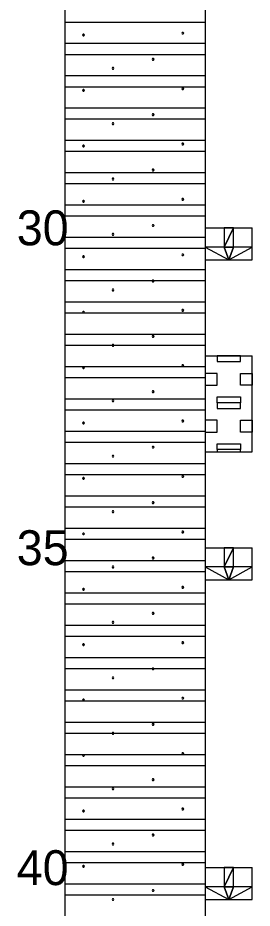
# Model space of a CAD drawing. Extents: x 2150161.5 to 2150203.1, y 143779.5 to 143868.5.
# Drawn here: x 2150192.011 to 2150192.844, y 143846.209 to 143849.371 of the extents above; entities that cross this region are included whole.
import ezdxf

# ---------------------------------------------------------------- set-up
doc = ezdxf.new("R2010")
doc.units = 0
doc.layers.add('Default', color=7, linetype='Continuous')

msp = doc.modelspace()

# ---------------------------------------------------------------- linework, layer by layer
at = {"layer": 'Default'}
for points in [[(2150192.1772, 143855.4435), (2150192.1772, 143843.2844)], [(2150192.6772, 143855.4435), (2150192.6772, 143843.2844)], [(2150192.1772, 143849.3564), (2150192.6772, 143849.3564)], [(2150192.2476, 143849.3102), (2150192.2459, 143849.313), (2150192.2427, 143849.313), (2150192.241, 143849.3102), (2150192.2427, 143849.3073), (2150192.2459, 143849.3073), (2150192.2476, 143849.3102)], [(2150192.6003, 143849.3167), (2150192.5987, 143849.3196), (2150192.5954, 143849.3196), (2150192.5938, 143849.3167), (2150192.5954, 143849.3139), (2150192.5987, 143849.3139), (2150192.6003, 143849.3167)], [(2150192.1772, 143849.2809), (2150192.6772, 143849.2809)], [(2150192.1772, 143849.2415), (2150192.6772, 143849.2415)], [(2150192.4948, 143849.2242), (2150192.4932, 143849.227), (2150192.4899, 143849.227), (2150192.4883, 143849.2242), (2150192.4899, 143849.2213), (2150192.4932, 143849.2213), (2150192.4948, 143849.2242)], [(2150192.1772, 143849.1661), (2150192.6772, 143849.1661)], [(2150192.3522, 143849.1923), (2150192.3506, 143849.1952), (2150192.3473, 143849.1952), (2150192.3457, 143849.1923), (2150192.3473, 143849.1894), (2150192.3506, 143849.1894), (2150192.3522, 143849.1923)], [(2150192.1772, 143849.1267), (2150192.6772, 143849.1267)], [(2150192.2476, 143849.1133), (2150192.2459, 143849.1161), (2150192.2427, 143849.1161), (2150192.241, 143849.1133), (2150192.2427, 143849.1104), (2150192.2459, 143849.1104), (2150192.2476, 143849.1133)], [(2150192.6003, 143849.1198), (2150192.5987, 143849.1227), (2150192.5954, 143849.1227), (2150192.5938, 143849.1198), (2150192.5954, 143849.117), (2150192.5987, 143849.117), (2150192.6003, 143849.1198)], [(2150192.1772, 143849.0513), (2150192.6772, 143849.0513)], [(2150192.1772, 143849.0119), (2150192.6772, 143849.0119)], [(2150192.4948, 143849.0273), (2150192.4932, 143849.0301), (2150192.4899, 143849.0301), (2150192.4883, 143849.0273), (2150192.4899, 143849.0245), (2150192.4932, 143849.0245), (2150192.4948, 143849.0273)], [(2150192.3522, 143848.9954), (2150192.3506, 143848.9983), (2150192.3473, 143848.9983), (2150192.3457, 143848.9955), (2150192.3473, 143848.9926), (2150192.3506, 143848.9926), (2150192.3522, 143848.9954)], [(2150192.1772, 143848.9364), (2150192.6772, 143848.9364)], [(2150192.2476, 143848.9165), (2150192.2459, 143848.9193), (2150192.2427, 143848.9193), (2150192.241, 143848.9165), (2150192.2427, 143848.9136), (2150192.2459, 143848.9136), (2150192.2476, 143848.9165)], [(2150192.6003, 143848.923), (2150192.5987, 143848.9259), (2150192.5954, 143848.9259), (2150192.5938, 143848.923), (2150192.5954, 143848.9202), (2150192.5987, 143848.9202), (2150192.6003, 143848.923)], [(2150192.1772, 143848.8971), (2150192.6772, 143848.8971)], [(2150192.1772, 143848.8216), (2150192.6772, 143848.8216)], [(2150192.4948, 143848.8305), (2150192.4932, 143848.8333), (2150192.4899, 143848.8333), (2150192.4883, 143848.8305), (2150192.4899, 143848.8276), (2150192.4932, 143848.8276), (2150192.4948, 143848.8305)], [(2150192.3522, 143848.7986), (2150192.3506, 143848.8015), (2150192.3473, 143848.8015), (2150192.3457, 143848.7986), (2150192.3473, 143848.7957), (2150192.3506, 143848.7957), (2150192.3522, 143848.7986)], [(2150192.1772, 143848.7822), (2150192.6772, 143848.7822)], [(2150192.2476, 143848.7196), (2150192.2459, 143848.7224), (2150192.2427, 143848.7224), (2150192.241, 143848.7196), (2150192.2427, 143848.7167), (2150192.2459, 143848.7167), (2150192.2476, 143848.7196)], [(2150192.6003, 143848.7261), (2150192.5987, 143848.729), (2150192.5954, 143848.729), (2150192.5938, 143848.7261), (2150192.5954, 143848.7233), (2150192.5987, 143848.7233), (2150192.6003, 143848.7261)], [(2150192.1772, 143848.7068), (2150192.6772, 143848.7068)], [(2150192.1772, 143848.6674), (2150192.6772, 143848.6674)], [(2150192.4948, 143848.6336), (2150192.4932, 143848.6364), (2150192.4899, 143848.6364), (2150192.4883, 143848.6336), (2150192.4899, 143848.6308), (2150192.4932, 143848.6308), (2150192.4948, 143848.6336)], [(2150192.3522, 143848.6017), (2150192.3506, 143848.6046), (2150192.3473, 143848.6046), (2150192.3457, 143848.6018), (2150192.3473, 143848.5989), (2150192.3506, 143848.5989), (2150192.3522, 143848.6017)], [(2150192.6772, 143848.6253), (2150192.8438, 143848.6253)], [(2150192.8438, 143848.5117), (2150192.8438, 143848.6253)], [(2150192.1772, 143848.5919), (2150192.6772, 143848.5919)], [(2150192.1772, 143848.5526), (2150192.6772, 143848.5526)], [(2150192.2476, 143848.5228), (2150192.2459, 143848.5256), (2150192.2427, 143848.5256), (2150192.241, 143848.5228), (2150192.2427, 143848.5199), (2150192.2459, 143848.5199), (2150192.2476, 143848.5228)], [(2150192.6003, 143848.5293), (2150192.5987, 143848.5322), (2150192.5954, 143848.5322), (2150192.5938, 143848.5293), (2150192.5954, 143848.5265), (2150192.5987, 143848.5265), (2150192.6003, 143848.5293)], [(2150192.6772, 143848.5117), (2150192.8438, 143848.5117)], [(2150192.1772, 143848.4771), (2150192.6772, 143848.4771)], [(2150192.1772, 143848.4377), (2150192.6772, 143848.4377)], [(2150192.4948, 143848.4368), (2150192.4932, 143848.4396), (2150192.4899, 143848.4396), (2150192.4883, 143848.4368), (2150192.4899, 143848.4339), (2150192.4932, 143848.4339), (2150192.4948, 143848.4368)], [(2150192.3522, 143848.4049), (2150192.3506, 143848.4078), (2150192.3473, 143848.4078), (2150192.3457, 143848.4049), (2150192.3473, 143848.402), (2150192.3506, 143848.402), (2150192.3522, 143848.4049)], [(2150192.1772, 143848.3623), (2150192.6772, 143848.3623)], [(2150192.1772, 143848.3229), (2150192.6772, 143848.3229)], [(2150192.2476, 143848.3259), (2150192.2459, 143848.3287), (2150192.2427, 143848.3287), (2150192.241, 143848.3259), (2150192.2427, 143848.323), (2150192.2459, 143848.323), (2150192.2476, 143848.3259)], [(2150192.6003, 143848.3324), (2150192.5987, 143848.3353), (2150192.5954, 143848.3353), (2150192.5938, 143848.3324), (2150192.5954, 143848.3296), (2150192.5987, 143848.3296), (2150192.6003, 143848.3324)], [(2150192.1772, 143848.2474), (2150192.6772, 143848.2474)], [(2150192.4948, 143848.2399), (2150192.4932, 143848.2427), (2150192.4899, 143848.2427), (2150192.4883, 143848.2399), (2150192.4899, 143848.2371), (2150192.4932, 143848.2371), (2150192.4948, 143848.2399)], [(2150192.1772, 143848.2081), (2150192.6772, 143848.2081)], [(2150192.3522, 143848.208), (2150192.3506, 143848.2109), (2150192.3473, 143848.2109), (2150192.3457, 143848.2081), (2150192.3473, 143848.2052), (2150192.3506, 143848.2052), (2150192.3522, 143848.208)], [(2150192.6772, 143848.1708), (2150192.8438, 143848.1708)], [(2150192.8438, 143847.8299), (2150192.8438, 143848.1708)], [(2150192.1772, 143848.1326), (2150192.6772, 143848.1326)], [(2150192.2476, 143848.1291), (2150192.2459, 143848.1319), (2150192.2427, 143848.1319), (2150192.241, 143848.1291), (2150192.2427, 143848.1262), (2150192.2459, 143848.1262), (2150192.2476, 143848.1291)], [(2150192.6003, 143848.1356), (2150192.5987, 143848.1385), (2150192.5954, 143848.1385), (2150192.5938, 143848.1356), (2150192.5954, 143848.1328), (2150192.5987, 143848.1328), (2150192.6003, 143848.1356)], [(2150192.1772, 143848.0933), (2150192.6772, 143848.0933)], [(2150192.4948, 143848.0431), (2150192.4932, 143848.0459), (2150192.4899, 143848.0459), (2150192.4883, 143848.0431), (2150192.4899, 143848.0402), (2150192.4932, 143848.0402), (2150192.4948, 143848.0431)], [(2150192.1772, 143848.0178), (2150192.6772, 143848.0178)], [(2150192.3522, 143848.0112), (2150192.3506, 143848.0141), (2150192.3473, 143848.0141), (2150192.3457, 143848.0112), (2150192.3473, 143848.0083), (2150192.3506, 143848.0083), (2150192.3522, 143848.0112)], [(2150192.1772, 143847.9784), (2150192.6772, 143847.9784)], [(2150192.2476, 143847.9322), (2150192.2459, 143847.935), (2150192.2427, 143847.935), (2150192.241, 143847.9322), (2150192.2427, 143847.9293), (2150192.2459, 143847.9293), (2150192.2476, 143847.9322)], [(2150192.6003, 143847.9387), (2150192.5987, 143847.9416), (2150192.5954, 143847.9416), (2150192.5938, 143847.9387), (2150192.5954, 143847.9359), (2150192.5987, 143847.9359), (2150192.6003, 143847.9387)], [(2150192.1772, 143847.903), (2150192.6772, 143847.903)], [(2150192.1772, 143847.8636), (2150192.6772, 143847.8636)], [(2150192.4948, 143847.8462), (2150192.4932, 143847.849), (2150192.4899, 143847.849), (2150192.4883, 143847.8462), (2150192.4899, 143847.8434), (2150192.4932, 143847.8434), (2150192.4948, 143847.8462)], [(2150192.3522, 143847.8143), (2150192.3506, 143847.8172), (2150192.3473, 143847.8172), (2150192.3457, 143847.8144), (2150192.3473, 143847.8115), (2150192.3506, 143847.8115), (2150192.3522, 143847.8143)], [(2150192.6772, 143847.8299), (2150192.8438, 143847.8299)], [(2150192.1772, 143847.7881), (2150192.6772, 143847.7881)], [(2150192.1772, 143847.7488), (2150192.6772, 143847.7488)], [(2150192.6003, 143847.7419), (2150192.5987, 143847.7448), (2150192.5954, 143847.7448), (2150192.5938, 143847.7419), (2150192.5954, 143847.7391), (2150192.5987, 143847.7391), (2150192.6003, 143847.7419)], [(2150192.2476, 143847.7354), (2150192.2459, 143847.7382), (2150192.2427, 143847.7382), (2150192.241, 143847.7354), (2150192.2427, 143847.7325), (2150192.2459, 143847.7325), (2150192.2476, 143847.7354)], [(2150192.1772, 143847.6733), (2150192.6772, 143847.6733)], [(2150192.4948, 143847.6494), (2150192.4932, 143847.6522), (2150192.4899, 143847.6522), (2150192.4883, 143847.6494), (2150192.4899, 143847.6465), (2150192.4932, 143847.6465), (2150192.4948, 143847.6494)], [(2150192.1772, 143847.6339), (2150192.6772, 143847.6339)], [(2150192.3522, 143847.6175), (2150192.3506, 143847.6204), (2150192.3473, 143847.6204), (2150192.3457, 143847.6175), (2150192.3473, 143847.6146), (2150192.3506, 143847.6146), (2150192.3522, 143847.6175)], [(2150192.1772, 143847.5585), (2150192.6772, 143847.5585)], [(2150192.2476, 143847.5385), (2150192.2459, 143847.5413), (2150192.2427, 143847.5413), (2150192.241, 143847.5385), (2150192.2427, 143847.5356), (2150192.2459, 143847.5356), (2150192.2476, 143847.5385)], [(2150192.6003, 143847.545), (2150192.5987, 143847.5479), (2150192.5954, 143847.5479), (2150192.5938, 143847.545), (2150192.5954, 143847.5422), (2150192.5987, 143847.5422), (2150192.6003, 143847.545)], [(2150192.1772, 143847.5191), (2150192.6772, 143847.5191)], [(2150192.6772, 143847.489), (2150192.8438, 143847.489)], [(2150192.8438, 143847.3753), (2150192.8438, 143847.489)], [(2150192.1772, 143847.4436), (2150192.6772, 143847.4436)], [(2150192.4948, 143847.4525), (2150192.4932, 143847.4553), (2150192.4899, 143847.4553), (2150192.4883, 143847.4525), (2150192.4899, 143847.4497), (2150192.4932, 143847.4497), (2150192.4948, 143847.4525)], [(2150192.1772, 143847.4043), (2150192.6772, 143847.4043)], [(2150192.3522, 143847.4206), (2150192.3506, 143847.4235), (2150192.3473, 143847.4235), (2150192.3457, 143847.4207), (2150192.3473, 143847.4178), (2150192.3506, 143847.4178), (2150192.3522, 143847.4206)], [(2150192.6772, 143847.3753), (2150192.8438, 143847.3753)], [(2150192.2476, 143847.3417), (2150192.2459, 143847.3445), (2150192.2427, 143847.3445), (2150192.241, 143847.3417), (2150192.2427, 143847.3388), (2150192.2459, 143847.3388), (2150192.2476, 143847.3417)], [(2150192.6003, 143847.3482), (2150192.5987, 143847.3511), (2150192.5954, 143847.3511), (2150192.5938, 143847.3482), (2150192.5954, 143847.3454), (2150192.5987, 143847.3454), (2150192.6003, 143847.3482)], [(2150192.1772, 143847.3288), (2150192.6772, 143847.3288)], [(2150192.1772, 143847.2894), (2150192.6772, 143847.2894)], [(2150192.4948, 143847.2557), (2150192.4932, 143847.2585), (2150192.4899, 143847.2585), (2150192.4883, 143847.2557), (2150192.4899, 143847.2528), (2150192.4932, 143847.2528), (2150192.4948, 143847.2557)], [(2150192.1772, 143847.214), (2150192.6772, 143847.214)], [(2150192.3522, 143847.2238), (2150192.3506, 143847.2267), (2150192.3473, 143847.2267), (2150192.3457, 143847.2238), (2150192.3473, 143847.2209), (2150192.3506, 143847.2209), (2150192.3522, 143847.2238)], [(2150192.1772, 143847.1746), (2150192.6772, 143847.1746)], [(2150192.2476, 143847.1448), (2150192.2459, 143847.1476), (2150192.2427, 143847.1476), (2150192.241, 143847.1448), (2150192.2427, 143847.1419), (2150192.2459, 143847.1419), (2150192.2476, 143847.1448)], [(2150192.6003, 143847.1513), (2150192.5987, 143847.1542), (2150192.5954, 143847.1542), (2150192.5938, 143847.1513), (2150192.5954, 143847.1485), (2150192.5987, 143847.1485), (2150192.6003, 143847.1513)], [(2150192.1772, 143847.0992), (2150192.6772, 143847.0992)], [(2150192.1772, 143847.0598), (2150192.6772, 143847.0598)], [(2150192.4948, 143847.0588), (2150192.4932, 143847.0616), (2150192.4899, 143847.0616), (2150192.4883, 143847.0588), (2150192.4899, 143847.056), (2150192.4932, 143847.056), (2150192.4948, 143847.0588)], [(2150192.3522, 143847.0269), (2150192.3506, 143847.0298), (2150192.3473, 143847.0298), (2150192.3457, 143847.027), (2150192.3473, 143847.0241), (2150192.3506, 143847.0241), (2150192.3522, 143847.0269)], [(2150192.1772, 143846.9843), (2150192.6772, 143846.9843)], [(2150192.6003, 143846.9545), (2150192.5987, 143846.9574), (2150192.5954, 143846.9574), (2150192.5938, 143846.9545), (2150192.5954, 143846.9517), (2150192.5987, 143846.9517), (2150192.6003, 143846.9545)], [(2150192.1772, 143846.945), (2150192.6772, 143846.945)], [(2150192.2476, 143846.948), (2150192.2459, 143846.9508), (2150192.2427, 143846.9508), (2150192.241, 143846.948), (2150192.2427, 143846.9451), (2150192.2459, 143846.9451), (2150192.2476, 143846.948)], [(2150192.1772, 143846.8695), (2150192.6772, 143846.8695)], [(2150192.4948, 143846.862), (2150192.4932, 143846.8648), (2150192.4899, 143846.8648), (2150192.4883, 143846.862), (2150192.4899, 143846.8591), (2150192.4932, 143846.8591), (2150192.4948, 143846.862)], [(2150192.1772, 143846.8301), (2150192.6772, 143846.8301)], [(2150192.3522, 143846.8301), (2150192.3506, 143846.833), (2150192.3473, 143846.833), (2150192.3457, 143846.8301), (2150192.3473, 143846.8272), (2150192.3506, 143846.8272), (2150192.3522, 143846.8301)], [(2150192.1772, 143846.7547), (2150192.6772, 143846.7547)], [(2150192.2476, 143846.7511), (2150192.2459, 143846.7539), (2150192.2427, 143846.7539), (2150192.241, 143846.7511), (2150192.2427, 143846.7482), (2150192.2459, 143846.7482), (2150192.2476, 143846.7511)], [(2150192.6003, 143846.7576), (2150192.5987, 143846.7605), (2150192.5954, 143846.7605), (2150192.5938, 143846.7576), (2150192.5954, 143846.7548), (2150192.5987, 143846.7548), (2150192.6003, 143846.7576)], [(2150192.1772, 143846.7153), (2150192.6772, 143846.7153)], [(2150192.4948, 143846.6651), (2150192.4932, 143846.6679), (2150192.4899, 143846.6679), (2150192.4883, 143846.6651), (2150192.4899, 143846.6623), (2150192.4932, 143846.6623), (2150192.4948, 143846.6651)], [(2150192.1772, 143846.6398), (2150192.6772, 143846.6398)], [(2150192.3522, 143846.6332), (2150192.3506, 143846.6361), (2150192.3473, 143846.6361), (2150192.3457, 143846.6333), (2150192.3473, 143846.6304), (2150192.3506, 143846.6304), (2150192.3522, 143846.6332)], [(2150192.1772, 143846.6005), (2150192.6772, 143846.6005)], [(2150192.2476, 143846.5543), (2150192.2459, 143846.5571), (2150192.2427, 143846.5571), (2150192.241, 143846.5543), (2150192.2427, 143846.5514), (2150192.2459, 143846.5514), (2150192.2476, 143846.5543)], [(2150192.6003, 143846.5608), (2150192.5987, 143846.5637), (2150192.5954, 143846.5637), (2150192.5938, 143846.5608), (2150192.5954, 143846.558), (2150192.5987, 143846.558), (2150192.6003, 143846.5608)], [(2150192.1772, 143846.525), (2150192.6772, 143846.525)], [(2150192.1772, 143846.4856), (2150192.6772, 143846.4856)], [(2150192.4948, 143846.4683), (2150192.4932, 143846.4711), (2150192.4899, 143846.4711), (2150192.4883, 143846.4683), (2150192.4899, 143846.4654), (2150192.4932, 143846.4654), (2150192.4948, 143846.4683)], [(2150192.3522, 143846.4364), (2150192.3506, 143846.4393), (2150192.3473, 143846.4393), (2150192.3457, 143846.4364), (2150192.3473, 143846.4335), (2150192.3506, 143846.4335), (2150192.3522, 143846.4364)], [(2150192.1772, 143846.4102), (2150192.6772, 143846.4102)], [(2150192.1772, 143846.3708), (2150192.6772, 143846.3708)], [(2150192.2476, 143846.3574), (2150192.2459, 143846.3602), (2150192.2427, 143846.3602), (2150192.241, 143846.3574), (2150192.2427, 143846.3545), (2150192.2459, 143846.3545), (2150192.2476, 143846.3574)], [(2150192.6003, 143846.3639), (2150192.5987, 143846.3668), (2150192.5954, 143846.3668), (2150192.5938, 143846.3639), (2150192.5954, 143846.3611), (2150192.5987, 143846.3611), (2150192.6003, 143846.3639)], [(2150192.6772, 143846.3526), (2150192.8438, 143846.3526)], [(2150192.8438, 143846.239), (2150192.8438, 143846.3526)], [(2150192.1772, 143846.2954), (2150192.6772, 143846.2954)], [(2150192.1772, 143846.256), (2150192.6772, 143846.256)], [(2150192.4948, 143846.2714), (2150192.4932, 143846.2742), (2150192.4899, 143846.2742), (2150192.4883, 143846.2714), (2150192.4899, 143846.2686), (2150192.4932, 143846.2686), (2150192.4948, 143846.2714)], [(2150192.3522, 143846.2395), (2150192.3506, 143846.2424), (2150192.3473, 143846.2424), (2150192.3457, 143846.2396), (2150192.3473, 143846.2367), (2150192.3506, 143846.2367), (2150192.3522, 143846.2395)], [(2150192.6772, 143846.239), (2150192.8438, 143846.239)]]:
    msp.add_lwpolyline(points, dxfattribs=at)
for points in [[(2150192.7438, 143848.5572), (2150192.7772, 143848.5572), (2150192.7772, 143848.6253), (2150192.7438, 143848.5572)], [(2150192.7438, 143848.5572), (2150192.7772, 143848.6253), (2150192.7438, 143848.6253), (2150192.7438, 143848.5572)], [(2150192.7438, 143848.5572), (2150192.6772, 143848.5572), (2150192.7605, 143848.5117), (2150192.7438, 143848.5572)], [(2150192.7438, 143848.5572), (2150192.7605, 143848.5117), (2150192.7772, 143848.5572), (2150192.7438, 143848.5572)], [(2150192.7605, 143848.5117), (2150192.8438, 143848.5572), (2150192.7772, 143848.5572), (2150192.7605, 143848.5117)], [(2150192.7188, 143848.1708), (2150192.7188, 143848.15), (2150192.8022, 143848.15), (2150192.8022, 143848.1708)], [(2150192.6772, 143848.0666), (2150192.7188, 143848.0666), (2150192.7188, 143848.1083), (2150192.6772, 143848.1083)], [(2150192.8438, 143848.0666), (2150192.8022, 143848.0666), (2150192.8022, 143848.1083), (2150192.8438, 143848.1083)], [(2150192.7188, 143848.0041), (2150192.7188, 143848.025), (2150192.8022, 143848.025), (2150192.8022, 143848.0041)], [(2150192.7188, 143848.0041), (2150192.7188, 143847.9833), (2150192.8022, 143847.9833), (2150192.8022, 143848.0041)], [(2150192.6772, 143847.9), (2150192.7188, 143847.9), (2150192.7188, 143847.9416), (2150192.6772, 143847.9416)], [(2150192.8438, 143847.9), (2150192.8022, 143847.9), (2150192.8022, 143847.9416), (2150192.8438, 143847.9416)], [(2150192.7188, 143847.8375), (2150192.7188, 143847.8583), (2150192.8022, 143847.8583), (2150192.8022, 143847.8375)], [(2150192.8022, 143847.8375), (2150192.7188, 143847.8375), (2150192.7188, 143847.8299), (2150192.8022, 143847.8299)], [(2150192.7438, 143847.4208), (2150192.7772, 143847.4208), (2150192.7772, 143847.489), (2150192.7438, 143847.4208)], [(2150192.7438, 143847.4208), (2150192.7772, 143847.489), (2150192.7438, 143847.489), (2150192.7438, 143847.4208)], [(2150192.7438, 143847.4208), (2150192.6772, 143847.4208), (2150192.7605, 143847.3753), (2150192.7438, 143847.4208)], [(2150192.7438, 143847.4208), (2150192.7605, 143847.3753), (2150192.7772, 143847.4208), (2150192.7438, 143847.4208)], [(2150192.7605, 143847.3753), (2150192.8438, 143847.4208), (2150192.7772, 143847.4208), (2150192.7605, 143847.3753)], [(2150192.7438, 143846.2844), (2150192.7772, 143846.2844), (2150192.7772, 143846.3526), (2150192.7438, 143846.2844)], [(2150192.7438, 143846.2844), (2150192.7772, 143846.3526), (2150192.7438, 143846.3526), (2150192.7438, 143846.2844)], [(2150192.7438, 143846.2844), (2150192.6772, 143846.2844), (2150192.7605, 143846.239), (2150192.7438, 143846.2844)], [(2150192.7438, 143846.2844), (2150192.7605, 143846.239), (2150192.7772, 143846.2844), (2150192.7438, 143846.2844)], [(2150192.7605, 143846.239), (2150192.8438, 143846.2844), (2150192.7772, 143846.2844), (2150192.7605, 143846.239)]]:
    msp.add_lwpolyline(points, close=True, dxfattribs=at)

# ---------------------------------------------------------------- texts
for s, p in [('30', (2150192.0068, 143848.5633)), ('35', (2150192.0068, 143847.427)), ('40', (2150192.0068, 143846.2906))]:
    msp.add_text(s, height=0.124, dxfattribs=at).set_placement(p)

doc.saveas('drawing.dxf')
